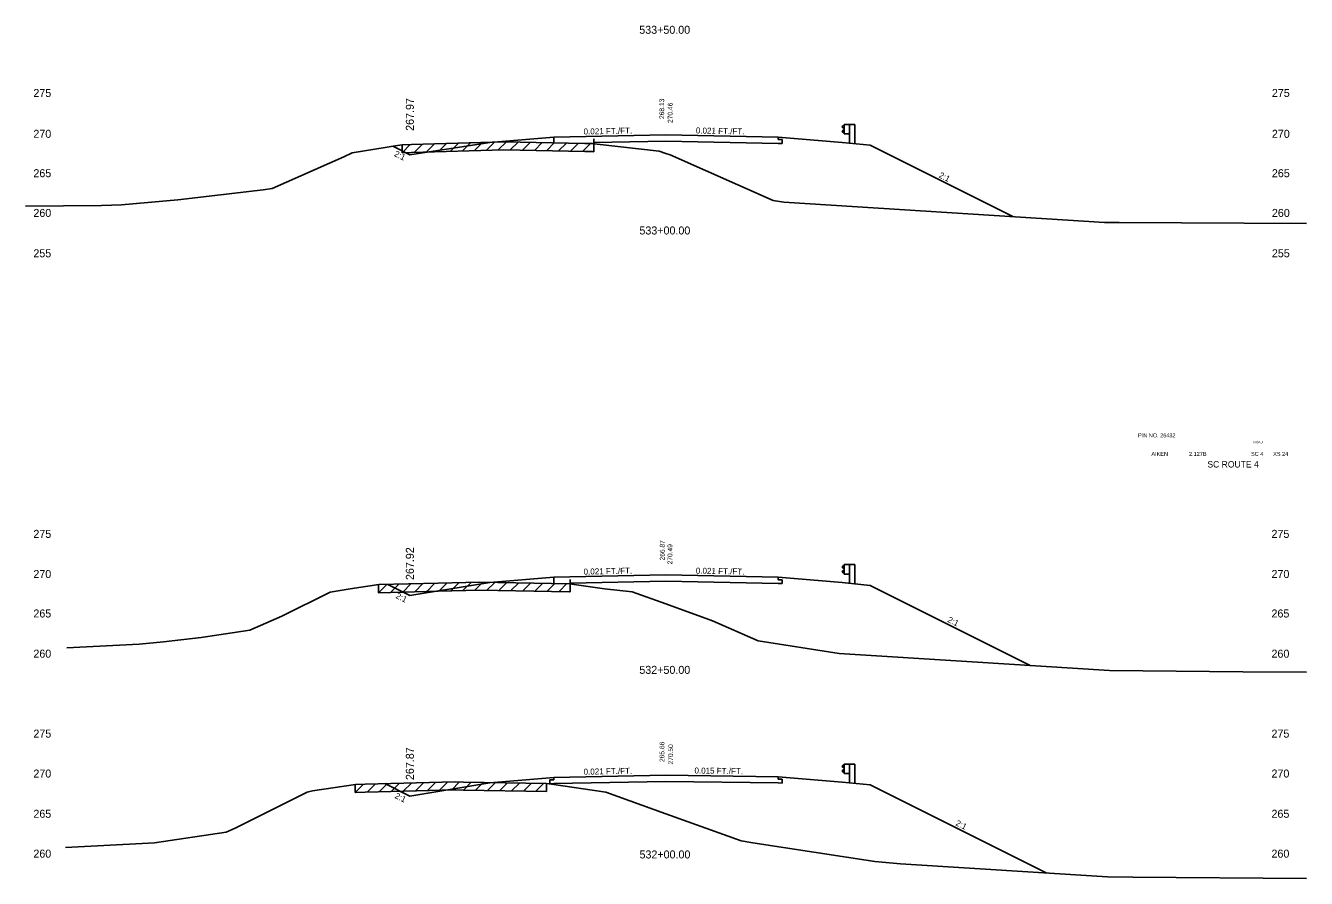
# Model space of a CAD drawing. Extents: x 883 to 1160, y 1002 to 4323.
# Drawn here: x 1000 to 1160, y 3692.6 to 3799.1 of the extents above; entities that cross this region are included whole.
import ezdxf

# ---------------------------------------------------------------- set-up
doc = ezdxf.new("R2010")
doc.units = 0
for name, color, linetype in [('Level 1', 7, 'Continuous'), ('Level 10', 7, 'Continuous'), ('Level 11', 7, 'Continuous'), ('Level 12', 7, 'Continuous'), ('Level 24', 7, 'Continuous'), ('Level 3', 7, 'Continuous'), ('Level 32', 7, 'Continuous'), ('Level 33', 7, 'Continuous'), ('Level 53', 7, 'Continuous'), ('Level 59', 7, 'Continuous'), ('Level 6', 7, 'Continuous'), ('Level 60', 7, 'Continuous'), ('Level 61', 7, 'Continuous'), ('Level 7', 7, 'Continuous')]:
    doc.layers.add(name, color=color, linetype=linetype)

msp = doc.modelspace()

# ---------------------------------------------------------------- linework, layer by layer
at = {"layer": 'Level 11'}
for p, q in [((1066, 3784.46), (1066, 3785.17)), ((1094, 3784.87), (1094, 3785.17)), ((1094.5, 3784.85), (1094, 3784.87)), ((1094, 3784.39), (1094.5, 3784.37)), ((1094.5, 3784.37), (1094.5, 3784.85)), ((1066, 3729.44), (1066, 3730.2)), ((1094, 3729.9), (1094, 3730.2)), ((1094.5, 3729.89), (1094, 3729.9)), ((1094.5, 3729.41), (1094.5, 3729.89)), ((1094, 3729.42), (1094.5, 3729.41)), ((1066, 3704.91), (1065.5, 3704.9)), ((1065.5, 3704.9), (1065.5, 3704.42)), ((1065.5, 3704.42), (1066, 3704.43)), ((1066, 3705.21), (1066, 3704.91)), ((1094, 3705), (1094, 3705.3)), ((1094.5, 3704.99), (1094, 3705)), ((1094, 3704.52), (1094.5, 3704.51)), ((1094.5, 3704.51), (1094.5, 3704.99))]:
    msp.add_line(p, q, dxfattribs=at)
at = {"layer": 'Level 12'}
for p, q in [((1070.97, 3784.49), (1080, 3784.68)), ((1070.97, 3784.34), (1070.97, 3784.49)), ((1080, 3784.68), (1094, 3784.39)), ((1068.02, 3729.46), (1080, 3729.71)), ((1080, 3729.71), (1094, 3729.42)), ((1068.02, 3729.39), (1068.02, 3729.46)), ((1080, 3704.72), (1066, 3704.43)), ((1094, 3704.52), (1080, 3704.72))]:
    msp.add_line(p, q, dxfattribs=at)
at = {"layer": 'Level 24'}
for p, q in [((1102.27, 3786.68), (1102, 3786.48)), ((1102, 3786.48), (1102, 3786.43)), ((1102, 3786.43), (1102.27, 3786.23)), ((1102, 3785.9), (1102.27, 3786.1)), ((1102, 3785.85), (1102, 3785.9)), ((1102.27, 3785.65), (1102, 3785.85)), ((1102.27, 3785.58), (1102.27, 3786.75)), ((1102.27, 3786.75), (1102.94, 3786.75)), ((1102.94, 3786.75), (1102.94, 3784.4)), ((1102.94, 3786.75), (1103.6, 3786.75)), ((1103.6, 3786.75), (1103.6, 3784.34)), ((1102.27, 3785.58), (1102.94, 3785.58)), ((1102.27, 3731.71), (1102, 3731.51)), ((1102, 3731.51), (1102, 3731.46)), ((1102, 3731.46), (1102.27, 3731.26)), ((1102.27, 3730.61), (1102.27, 3731.78)), ((1102.27, 3731.78), (1102.94, 3731.78)), ((1102.94, 3731.78), (1102.94, 3729.44)), ((1102.94, 3731.78), (1103.6, 3731.78)), ((1103.6, 3731.78), (1103.6, 3729.37)), ((1102, 3730.94), (1102.27, 3731.14)), ((1102, 3730.89), (1102, 3730.94)), ((1102.27, 3730.69), (1102, 3730.89)), ((1102.27, 3730.61), (1102.94, 3730.61)), ((1102.27, 3706.81), (1102, 3706.61)), ((1102, 3706.61), (1102, 3706.56)), ((1102, 3706.56), (1102.27, 3706.36)), ((1102, 3706.04), (1102.27, 3706.24)), ((1102, 3705.99), (1102, 3706.04)), ((1102.27, 3705.79), (1102, 3705.99)), ((1102.27, 3705.71), (1102.27, 3706.88)), ((1102.27, 3706.88), (1102.94, 3706.88)), ((1102.27, 3705.71), (1102.94, 3705.71)), ((1102.94, 3706.88), (1102.94, 3704.54)), ((1102.94, 3706.88), (1103.6, 3706.88)), ((1103.6, 3706.88), (1103.6, 3704.47))]:
    msp.add_line(p, q, dxfattribs=at)
at = {"layer": 'Level 53'}
for p, q in [((1070.97, 3784.97), (1070.97, 3784.34)), ((1068.02, 3729.94), (1068.02, 3729.39))]:
    msp.add_line(p, q, dxfattribs=at)
at = {"layer": 'Level 59'}
for p, q in [((1066, 3785.17), (1080, 3785.46)), ((1080, 3785.46), (1094, 3785.17)), ((1066, 3730.2), (1080, 3730.49)), ((1080, 3730.49), (1094, 3730.2)), ((1066, 3705.21), (1080, 3705.5)), ((1080, 3705.5), (1094, 3705.3))]:
    msp.add_line(p, q, dxfattribs=at)
at = {"layer": 'Level 6'}
for p, q in [((1058, 3784.5), (1066, 3785.17)), ((1094, 3785.17), (1102, 3784.5)), ((1102, 3784.5), (1105.5, 3784.15)), ((1058, 3729.53), (1066, 3730.2)), ((1094, 3730.2), (1102, 3729.53)), ((1102, 3729.53), (1105.5, 3729.18)), ((1058, 3704.54), (1066, 3705.21)), ((1094, 3705.3), (1102, 3704.63)), ((1102, 3704.63), (1105.5, 3704.28))]:
    msp.add_line(p, q, dxfattribs=at)
at = {"layer": 'Level 60'}
for p, q in [((1040.79, 3783.22), (1046.44, 3784.13)), ((1046.44, 3784.13), (1047.02, 3784.21)), ((1047.02, 3784.21), (1048.22, 3784.24)), ((1048.22, 3784.24), (1059.74, 3784.58)), ((1059.74, 3784.58), (1069.88, 3784.38)), ((1069.88, 3784.38), (1070.81, 3784.37)), ((1070.81, 3784.37), (1071.42, 3784.28)), ((1071.42, 3784.28), (1079.16, 3783.43)), ((1030.78, 3778.76), (1039.77, 3782.72)), ((1039.77, 3782.72), (1040.79, 3783.22)), ((1079.16, 3783.43), (1080, 3783.13)), ((1080, 3783.13), (1080.52, 3782.94)), ((1080.52, 3782.94), (1093.4, 3777.24)), ((1019, 3777.35), (1029.68, 3778.6)), ((1029.68, 3778.6), (1030.78, 3778.76)), ((1000, 3776.55), (1009.5, 3776.61)), ((1009.5, 3776.61), (1011.99, 3776.73)), ((1011.99, 3776.73), (1019, 3777.35)), ((1093.4, 3777.24), (1094.72, 3777.04)), ((1094.72, 3777.04), (1132.82, 3774.64)), ((1132.82, 3774.64), (1134.76, 3774.52)), ((1134.76, 3774.52), (1136.63, 3774.5)), ((1136.63, 3774.5), (1160, 3774.38)), ((1051.53, 3729.46), (1056.71, 3729.61)), ((1056.71, 3729.61), (1061.26, 3729.52)), ((1032.01, 3725.33), (1038.05, 3728.34)), ((1038.05, 3728.34), (1040.56, 3728.75)), ((1040.56, 3728.75), (1044.13, 3729.28)), ((1044.13, 3729.28), (1051.53, 3729.46)), ((1061.26, 3729.52), (1067.96, 3729.4)), ((1067.96, 3729.4), (1072.31, 3728.77)), ((1072.31, 3728.77), (1075.79, 3728.39)), ((1075.79, 3728.39), (1080, 3726.87)), ((1080, 3726.87), (1085.8, 3724.77)), ((1028.03, 3723.58), (1032.01, 3725.33)), ((1021.93, 3722.67), (1028.03, 3723.58)), ((1085.8, 3724.77), (1091.51, 3722.25)), ((1005.15, 3721.4), (1014.17, 3721.85)), ((1014.17, 3721.85), (1017.24, 3722.12)), ((1017.24, 3722.12), (1021.93, 3722.67)), ((1091.51, 3722.25), (1101.62, 3720.69)), ((1101.62, 3720.69), (1118.24, 3719.65)), ((1118.24, 3719.65), (1135.41, 3718.56)), ((1135.41, 3718.56), (1152.05, 3718.41)), ((1152.05, 3718.41), (1160, 3718.37)), ((1035.83, 3703.54), (1041.2, 3704.34)), ((1041.2, 3704.34), (1042.42, 3704.38)), ((1042.42, 3704.38), (1053.68, 3704.65)), ((1053.68, 3704.65), (1054.7, 3704.63)), ((1054.7, 3704.63), (1065.06, 3704.45)), ((1065.06, 3704.45), (1065.71, 3704.36)), ((1065.71, 3704.36), (1072.48, 3703.38)), ((1026.18, 3698.89), (1035.16, 3703.38)), ((1035.16, 3703.38), (1035.83, 3703.54)), ((1072.48, 3703.38), (1073.99, 3702.83)), ((1073.99, 3702.83), (1080, 3700.66)), ((1080, 3700.66), (1089.39, 3697.27)), ((1016.1, 3697.04), (1025.04, 3698.38)), ((1025.04, 3698.38), (1026.18, 3698.89)), ((1004.97, 3696.47), (1015.34, 3696.99)), ((1015.34, 3696.99), (1016.1, 3697.04)), ((1089.39, 3697.27), (1090.85, 3697.05)), ((1090.85, 3697.05), (1106.09, 3694.7)), ((1106.09, 3694.7), (1109.31, 3694.42)), ((1109.31, 3694.42), (1135.15, 3692.8)), ((1135.15, 3692.8), (1138.3, 3692.77)), ((1138.3, 3692.77), (1160, 3692.6))]:
    msp.add_line(p, q, dxfattribs=at)
at = {"layer": 'Level 61'}
for p, q in [((1048.06, 3784.24), (1047.03, 3783.21)), ((1047.03, 3784.21), (1047.03, 3783.21)), ((1049.56, 3784.28), (1048.53, 3783.25)), ((1051.07, 3784.32), (1050.04, 3783.29)), ((1052.57, 3784.37), (1051.54, 3783.34)), ((1054.07, 3784.41), (1053.04, 3783.38)), ((1055.57, 3784.45), (1054.54, 3783.42)), ((1057.08, 3784.5), (1056.05, 3783.47)), ((1058.58, 3784.54), (1057.55, 3783.51)), ((1060.07, 3784.57), (1059.05, 3783.56)), ((1061.54, 3784.54), (1060.55, 3783.56)), ((1063.04, 3784.51), (1062.06, 3783.53)), ((1064.54, 3784.48), (1063.56, 3783.5)), ((1066.04, 3784.46), (1065.06, 3783.47)), ((1067.55, 3784.43), (1066.56, 3783.45)), ((1069.05, 3784.4), (1068.07, 3783.42)), ((1070.55, 3784.37), (1069.57, 3783.39)), ((1070.97, 3783.34), (1070.97, 3784.34)), ((1047.03, 3783.21), (1048.22, 3783.24)), ((1048.22, 3783.24), (1059.74, 3783.58)), ((1059.74, 3783.58), (1069.88, 3783.38)), ((1069.88, 3783.38), (1070.81, 3783.37)), ((1070.81, 3783.37), (1070.97, 3783.34)), ((1045.13, 3729.3), (1044.1, 3728.27)), ((1044.1, 3729.27), (1044.1, 3728.27)), ((1044.1, 3728.27), (1044.13, 3728.28)), ((1044.13, 3728.28), (1051.53, 3728.46)), ((1046.63, 3729.34), (1045.6, 3728.31)), ((1048.13, 3729.37), (1047.11, 3728.35)), ((1049.64, 3729.41), (1048.61, 3728.39)), ((1051.14, 3729.45), (1050.11, 3728.42)), ((1051.53, 3728.46), (1056.71, 3728.61)), ((1052.65, 3729.49), (1051.61, 3728.46)), ((1054.15, 3729.53), (1053.12, 3728.5)), ((1055.65, 3729.57), (1054.62, 3728.55)), ((1057.13, 3729.6), (1056.12, 3728.59)), ((1056.71, 3728.61), (1061.26, 3728.52)), ((1058.61, 3729.57), (1057.62, 3728.59)), ((1060.11, 3729.54), (1059.13, 3728.56)), ((1061.61, 3729.51), (1060.63, 3728.53)), ((1061.26, 3728.52), (1067.96, 3728.4)), ((1063.12, 3729.49), (1062.13, 3728.5)), ((1064.62, 3729.46), (1063.63, 3728.48)), ((1066.12, 3729.43), (1065.14, 3728.45)), ((1067.62, 3729.41), (1066.64, 3728.42)), ((1067.96, 3728.4), (1068.02, 3728.39)), ((1068.02, 3728.39), (1068.02, 3729.39)), ((1042.21, 3704.37), (1041.17, 3703.34)), ((1041.17, 3704.34), (1041.17, 3703.34)), ((1043.7, 3704.41), (1042.68, 3703.38)), ((1045.2, 3704.44), (1044.18, 3703.42)), ((1046.71, 3704.48), (1045.68, 3703.45)), ((1048.21, 3704.51), (1047.18, 3703.49)), ((1049.71, 3704.55), (1048.69, 3703.53)), ((1051.21, 3704.59), (1050.19, 3703.56)), ((1052.72, 3704.62), (1051.69, 3703.6)), ((1054.2, 3704.64), (1053.19, 3703.63)), ((1055.68, 3704.61), (1054.7, 3703.63)), ((1057.18, 3704.59), (1056.2, 3703.6)), ((1058.69, 3704.56), (1057.7, 3703.58)), ((1060.19, 3704.53), (1059.2, 3703.55)), ((1061.69, 3704.51), (1060.71, 3703.53)), ((1063.19, 3704.48), (1062.21, 3703.5)), ((1064.7, 3704.45), (1063.71, 3703.47)), ((1065.08, 3703.45), (1065.08, 3704.45)), ((1041.17, 3703.34), (1041.2, 3703.34)), ((1041.2, 3703.34), (1042.42, 3703.38)), ((1042.42, 3703.38), (1053.68, 3703.65)), ((1053.68, 3703.65), (1054.7, 3703.63)), ((1054.7, 3703.63), (1065.06, 3703.45)), ((1065.06, 3703.45), (1065.08, 3703.45))]:
    msp.add_line(p, q, dxfattribs=at)
at = {"layer": 'Level 7'}
for p, q in [((1045.87, 3784.04), (1048, 3782.97)), ((1048, 3782.97), (1058, 3784.5)), ((1105.5, 3784.15), (1123.32, 3775.24)), ((1045.24, 3729.3), (1048, 3727.92)), ((1048, 3727.92), (1058, 3729.53)), ((1105.5, 3729.18), (1125.49, 3719.19)), ((1044.88, 3704.43), (1048, 3702.88)), ((1048, 3702.88), (1058, 3704.54)), ((1105.5, 3704.28), (1127.49, 3693.28))]:
    msp.add_line(p, q, dxfattribs=at)

# ---------------------------------------------------------------- texts
at = {"layer": 'Level 1'}
for s, height, p in [('533+50.00', 1, (1076.66, 3798.07)), ('533+00.00', 1, (1076.68, 3773.01)), ('PIN NO. 26432', 0.5, (1138.97, 3747.67)), ('AIKEN', 0.5, (1140.64, 3745.36)), (' 2.127B', 0.5, (1145.15, 3745.36)), ('SC 4', 0.5, (1153.09, 3745.36)), ('XS 24', 0.5, (1155.85, 3745.36)), ('SC ROUTE 4', 0.8, (1147.63, 3743.91)), ('532+50.00', 1, (1076.67, 3718.14)), ('532+00.00', 1, (1076.69, 3695.09))]:
    msp.add_text(s, height=height, dxfattribs=at).set_placement(p)
at = {"layer": 'Level 10'}
for s, p in [('268.13', (1079.77, 3787.43)), ('266.87', (1079.83, 3732.3)), ('265.66', (1079.8, 3707.13))]:
    msp.add_text(s, height=0.6, rotation=90, dxfattribs=at).set_placement(p)
at = {"layer": 'Level 3'}
for s, height, p in [(' 275', 1, (1000.6, 3790.18)), (' 275', 1, (1155.32, 3790.18)), (' 270', 1, (1000.6, 3785.08)), (' 270', 1, (1155.32, 3785.08)), (' 265', 1, (1000.6, 3780.16)), (' 265', 1, (1155.32, 3780.16)), (' 260', 1, (1000.6, 3775.2)), (' 260', 1, (1155.32, 3775.2)), (' 255', 1, (1000.6, 3770.16)), (' 255', 1, (1155.32, 3770.16)), ('ROAD', 0.3, (1153.38, 3746.94)), (' 275', 1, (1000.6, 3735.12)), (' 275', 1, (1155.27, 3735.12)), (' 270', 1, (1000.6, 3730.11)), (' 270', 1, (1155.27, 3730.11)), (' 265', 1, (1000.6, 3725.18)), (' 265', 1, (1155.27, 3725.18)), (' 260', 1, (1000.6, 3720.16)), (' 260', 1, (1155.27, 3720.16)), (' 275', 1, (1000.6, 3710.18)), (' 275', 1, (1155.27, 3710.18)), (' 270', 1, (1000.6, 3705.19)), (' 270', 1, (1155.27, 3705.19)), (' 265', 1, (1000.6, 3700.17)), (' 265', 1, (1155.27, 3700.17)), (' 260', 1, (1000.6, 3695.19)), (' 260', 1, (1155.27, 3695.19))]:
    msp.add_text(s, height=height, dxfattribs=at).set_placement(p)
at = {"layer": 'Level 32'}
for s, rotation, p in [('0.021 FT./FT.', 1.1916, (1069.71, 3785.49)), ('0.021 FT./FT.', 358.8084, (1083.72, 3785.63)), ('2:1', 333.435, (1045.97, 3782.84)), ('2:1', 333.435, (1114.01, 3780.17)), ('0.021 FT./FT.', 1.1916, (1069.71, 3730.53)), ('0.021 FT./FT.', 358.8084, (1083.72, 3730.66)), ('2:1', 333.435, (1046.17, 3727.64)), ('2:1', 333.435, (1115.1, 3724.66)), ('0.021 FT./FT.', 1.1916, (1069.71, 3705.54)), ('0.015 FT./FT.', 359.1642, (1083.55, 3705.7)), ('2:1', 333.435, (1046.05, 3702.67)), ('2:1', 333.435, (1116.1, 3699.26))]:
    msp.add_text(s, height=0.75, rotation=rotation, dxfattribs=at).set_placement(p)
at = {"layer": 'Level 33'}
for s, p in [('267.97', (1048.5, 3785.95)), ('267.92', (1048.5, 3729.86)), ('267.87', (1048.5, 3704.88))]:
    msp.add_text(s, height=1, rotation=90, dxfattribs=at).set_placement(p)
at = {"layer": 'Level 59'}
for s, p in [(' 270.46', (1080.82, 3786.7)), (' 270.49', (1080.79, 3731.58)), (' 270.50', (1080.88, 3706.59))]:
    msp.add_text(s, height=0.6, rotation=90, dxfattribs=at).set_placement(p)

doc.saveas('drawing.dxf')
